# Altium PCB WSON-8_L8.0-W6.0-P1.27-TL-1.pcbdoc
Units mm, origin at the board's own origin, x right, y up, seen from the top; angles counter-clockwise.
Board outline 22.58 x 19.05 mm, 2 copper layers (Top Layer, Bottom Layer), stack 0 mm thick; 1 components, 0 nets, 9 pads, 0 vias.
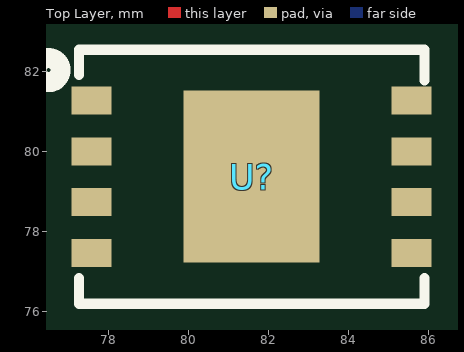
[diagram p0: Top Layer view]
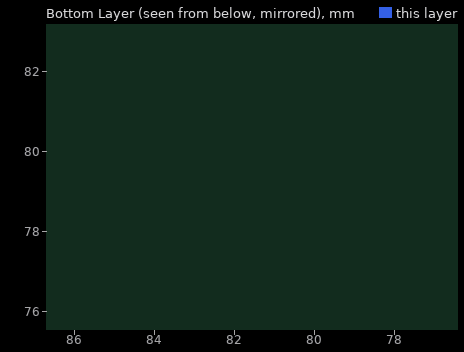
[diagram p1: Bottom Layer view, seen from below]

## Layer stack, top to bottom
Top Layer: signal copper (thickness not stored)
Bottom Layer: signal copper (thickness not stored)

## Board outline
92.43,69.85 69.85,69.85 69.85,88.9 92.43,88.9

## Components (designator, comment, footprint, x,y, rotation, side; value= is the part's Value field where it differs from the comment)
U? "" WSON-8_L8.0-W6.0-P1.27-TL-1 81.58,79.375 r0 top

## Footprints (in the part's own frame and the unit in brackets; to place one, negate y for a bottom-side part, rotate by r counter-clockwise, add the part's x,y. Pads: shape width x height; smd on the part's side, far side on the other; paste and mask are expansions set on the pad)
WSON-8_L8.0-W6.0-P1.27-TL-1 [mm]
  rect 1x0.7 smd paste+0 mask+0.05: 1(-4,1.905) 2(-4,0.635) 3(-4,-0.635) 4(-4,-1.905) 5(4,-1.905) 6(4,-0.635) 7(4,0.635) 8(4,1.905)
  rect 3.4x4.3 smd paste+0 mask+0.05: 9(0,0)
  silkscreen extent -5.38,-3.17 4.32,3.17

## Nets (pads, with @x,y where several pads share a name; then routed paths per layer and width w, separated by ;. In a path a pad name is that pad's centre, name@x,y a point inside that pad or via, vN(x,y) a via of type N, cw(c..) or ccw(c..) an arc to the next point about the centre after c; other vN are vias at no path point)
pads on no net: U?.1 U?.2 U?.3 U?.4 U?.5 U?.6 U?.7 U?.8 U?.9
